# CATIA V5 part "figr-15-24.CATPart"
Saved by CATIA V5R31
Part number: Part1
Bounding box of the stored display mesh (mm): x -50 to 50, y -25 to 25, z -24 to 1
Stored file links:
  D:\PROJECTS\Project 2021\US EDITION\CATIA V5 6R 2021\Resources\Part Files\c15_catia_v5_6r2021_prt\figr-15-24.CATPart
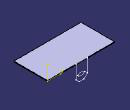
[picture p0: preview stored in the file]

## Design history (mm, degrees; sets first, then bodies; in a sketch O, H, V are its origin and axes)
SheetMetalParameters1: Thickness 1, BendRadius 2, KFactor 0.400515 {= log(min(100,max(20*SheetMetalParameters1.BendRadius,SheetMetalParameters1.Thickness)/SheetMetalParameters1.Thickness))/log(100)/2}, ReliefRadialLength 1, ReliefAxialLength 2, MinimumBendRadius 0
Body1 (main body)
  Sketch1 on xy-plane, origin (0, 0, 0), H (1, 0, 0), V (0, 1, 0)
    line L1 (-50, 25) -> (50, 25)
    line L2 (50, 25) -> (50, -25)
    line L3 (50, -25) -> (-50, -25)
    line L4 (-50, -25) -> (-50, 25)
    length L1 = 100
    distance V L2 = 50
    length L2 = 50
    distance H L3 = 25
    horizontal: L1 H, L3 H
    vertical: L2 V, L4 V
  Wall1: Thickness 1, Profile Sketch1
  Sketch2 on face of Wall1, origin (50, 25, 0), H (-1, 0, 0), V (0, 0, 1)
    line L1 (42.3549, 1) -> (42.3549, -19)
    point P2 (42.3549, -19)
    line L2 (42.3549, -19) -> (47.3549, -24)
    point P3 (47.3549, -24)
    line L3 (47.3549, -24) -> (54.3549, -24)
    point P4 (54.3549, -24)
    line L4 (54.3549, -24) -> (59.3549, -19)
    point P5 (59.3549, -19)
    line L5 (59.3549, -19) -> (59.3549, 1)
    line L6 (59.3549, 1) -> (42.3549, 1)
    reference projected line E1 (100, 1) -> (0, 1) from edge [face of Wall1 | face of Wall1]
    ellipse A1 centre (50.1164, -15.2153) semi-axes 5.0583, 2.1402 rotation 0
    length L5 = 20
    length L1 = 20
    length L3 = 7
    distance P4 L5 = 5
    distance P2 P3 H = 5
    distance L3 P5 = 5
    vertical: L1 V, L5 V
    horizontal: L3 H, L6 H
    coincidence: L6 E1
    parallelism: A1 L3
